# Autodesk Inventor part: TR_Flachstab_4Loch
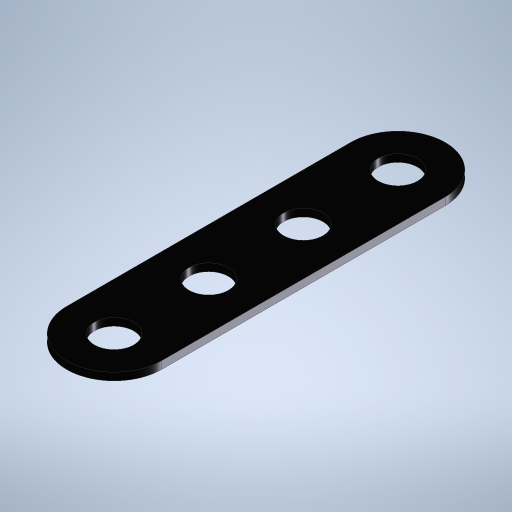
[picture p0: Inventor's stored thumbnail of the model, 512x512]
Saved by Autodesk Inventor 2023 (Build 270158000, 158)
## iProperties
Created: 2023-11
Part Number: TR_Flachstab_4Loch
Material: Edelstahl
Document SubType Name: Modeling
Designer: Admin
Density: 8 g/cm^3
Appearance: Halbpoliert
Author: Admin
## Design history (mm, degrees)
sketch "Skizze1"
  geometry: L1 (0, 15)-(0, -15); L2 (-5, 15)-(-5, -15); L3 (5, -15)-(5, 15); A1 r 5 centre (0, 15) between (5, 15) and (-5, 15); A2 r 5 centre (0, -15) between (-5, -15) and (5, -15); 3 further points
  constraints: 8 end point, 4 point on circle, 4 tangent, 2 centre point, 2 midpoint, 1 horizontal alignment, 1 parallel, 1 vertical, 1 vertical alignment
  dimensions: "d0" = 30 distance of L1.start L1.end (computed from Loch, Einheitsmaß); "d1" = 5 radius of A1 (= 0.5 x Einheitsmaß)
extrude "Extrusion1" new body sketch "Skizze1" distance "d5" = 0.8 (= Dicke); taper "d6" = 0 deg
sketch "Skizze2"
  geometry: C1 r 2.075 at (0, 15); A1 r 5 centre (0, 15) between (5, 15) and (-5, 15) reference; 1 further point
  constraints: 1 centre point, 1 coincident
  dimensions: "d7" = 4.15 diameter of C1 (= 2 x Radius)
extrude "Extrusion2" cut sketch "Skizze2" stored distance "d8" = 10; taper "d9" = 0 deg
pattern_linear "Rechteckige Anordnung1" dims "d12" = 10 (= Einheitsmaß)
node "Volumenkörper1"
other parameters: "Einheitsmaß" = 10 [user parameter; used in 3 equation terms], "Radius" = 2.075 [user parameter; used in 1 equation term], "Fasen" = 0.5 [user parameter], "Dicke" = 0.8 [user parameter; used in 1 equation term]
